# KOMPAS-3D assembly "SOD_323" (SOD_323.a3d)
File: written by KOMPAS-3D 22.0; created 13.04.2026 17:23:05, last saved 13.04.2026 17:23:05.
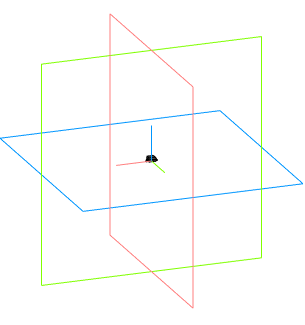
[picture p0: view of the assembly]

Document properties: Автор: Andrey; Полное имя файла: C:\Users\User1\Documents\SOD_323.a3d

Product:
- Component [assembly]: ASSEMBLY  | qty 1  | source file: ASSEMBLY_5.a3d
- Part/product: SOD_323
    Комментарий: SOD_323

Referenced files in C:\Users\User1\Documents\: ASSEMBLY_5.a3d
